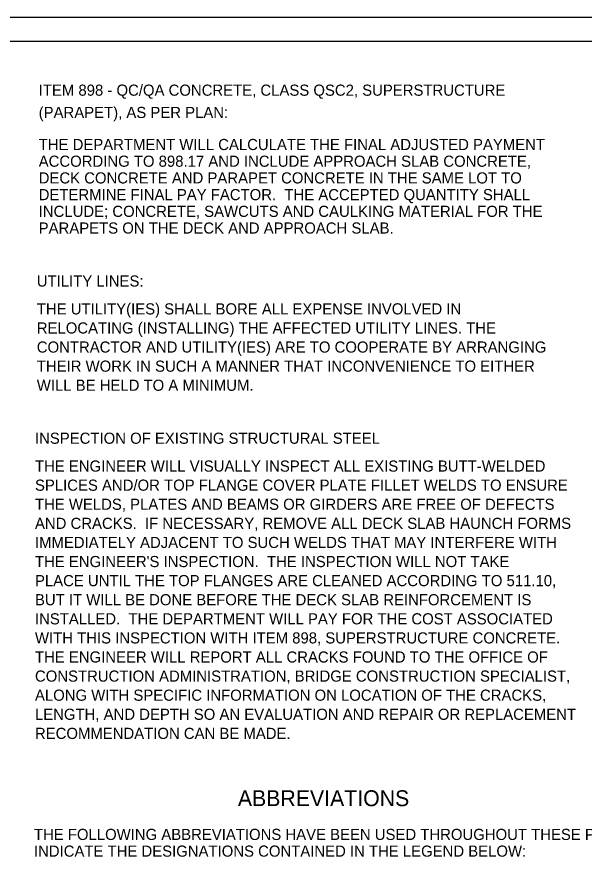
# Model space of a CAD drawing. Extents: x -70.8 to -34.9, y -11.1 to 10.9.
# Drawn here: x -46.33 to -39.19, y -0.16 to 10.66 of the extents above; entities that cross this region are included whole.
import ezdxf

# ---------------------------------------------------------------- set-up
doc = ezdxf.new("R2010")
doc.units = 0
for name, color, linetype in [('BR_P_Gen_Text', 7, 'Continuous'), ('SH_Border', 7, 'Continuous'), ('SH_Cut_Line', 7, 'Continuous'), ('SH_Data', 7, 'Continuous')]:
    doc.layers.add(name, color=color, linetype=linetype)

msp = doc.modelspace()

# ---------------------------------------------------------------- linework, layer by layer
at = {"layer": 'SH_Border'}
msp.add_lwpolyline([(-67.562, 10.356), (-36.062, 10.356), (-36.062, -10.644), (-67.562, -10.644)], close=True, dxfattribs=at)
at = {"layer": 'SH_Cut_Line'}
msp.add_lwpolyline([(-35.499, -10.994), (-69.499, -10.994), (-69.499, 10.656), (-35.499, 10.656)], close=True, dxfattribs=at)

# ---------------------------------------------------------------- texts
at = {"layer": 'BR_P_Gen_Text'}
for s, p in [('ITEM 898 - QC/QA CONCRETE, CLASS QSC2, SUPERSTRUCTURE', (-46.057, 9.669)), ('(PARAPET), AS PER PLAN:', (-46.057, 9.389)), ('THE DEPARTMENT WILL CALCULATE THE FINAL ADJUSTED PAYMENT ', (-46.057, 8.986)), ('ACCORDING TO 898.17 AND INCLUDE APPROACH SLAB CONCRETE, ', (-46.057, 8.776)), ('DECK CONCRETE AND PARAPET CONCRETE IN THE SAME LOT TO ', (-46.057, 8.566)), ('DETERMINE FINAL PAY FACTOR.  THE ACCEPTED QUANTITY SHALL ', (-46.057, 8.356)), ('INCLUDE; CONCRETE, SAWCUTS AND CAULKING MATERIAL FOR THE ', (-46.057, 8.146)), ('PARAPETS ON THE DECK AND APPROACH SLAB.', (-46.057, 7.936)), ('UTILITY LINES:', (-46.081, 7.27)), ('THE UTILITY(IES) SHALL BORE ALL EXPENSE INVOLVED IN ', (-46.081, 6.92)), ('RELOCATING (INSTALLING) THE AFFECTED UTILITY LINES. THE ', (-46.081, 6.68)), ('CONTRACTOR AND UTILITY(IES) ARE TO COOPERATE BY ARRANGING ', (-46.081, 6.44)), ('THEIR WORK IN SUCH A MANNER THAT INCONVENIENCE TO EITHER ', (-46.081, 6.2)), ('WILL BE HELD TO A MINIMUM.', (-46.081, 5.96)), ('INSPECTION OF EXISTING STRUCTURAL STEEL', (-46.104, 5.294)), ('THE ENGINEER WILL VISUALLY INSPECT ALL EXISTING BUTT-WELDED ', (-46.104, 4.944)), ('SPLICES AND/OR TOP FLANGE COVER PLATE FILLET WELDS TO ENSURE ', (-46.104, 4.704)), ('THE WELDS, PLATES AND BEAMS OR GIRDERS ARE FREE OF DEFECTS ', (-46.104, 4.464)), ('AND CRACKS.  IF NECESSARY, REMOVE ALL DECK SLAB HAUNCH FORMS ', (-46.104, 4.224)), ('IMMEDIATELY ADJACENT TO SUCH WELDS THAT MAY INTERFERE WITH ', (-46.104, 3.984)), ("THE ENGINEER'S INSPECTION.  THE INSPECTION WILL NOT TAKE ", (-46.104, 3.744)), ('PLACE UNTIL THE TOP FLANGES ARE CLEANED ACCORDING TO 511.10, ', (-46.104, 3.504)), ('BUT IT WILL BE DONE BEFORE THE DECK SLAB REINFORCEMENT IS ', (-46.104, 3.264)), ('INSTALLED.  THE DEPARTMENT WILL PAY FOR THE COST ASSOCIATED ', (-46.104, 3.024)), ('WITH THIS INSPECTION WITH ITEM 898, SUPERSTRUCTURE CONCRETE. ', (-46.104, 2.784)), ('THE ENGINEER WILL REPORT ALL CRACKS FOUND TO THE OFFICE OF ', (-46.104, 2.544)), ('CONSTRUCTION ADMINISTRATION, BRIDGE CONSTRUCTION SPECIALIST, ', (-46.104, 2.304)), ('ALONG WITH SPECIFIC INFORMATION ON LOCATION OF THE CRACKS, ', (-46.104, 2.064)), ('LENGTH, AND DEPTH SO AN EVALUATION AND REPAIR OR REPLACEMENT ', (-46.104, 1.824)), ('RECOMMENDATION CAN BE MADE.', (-46.104, 1.584))]:
    msp.add_text(s, height=0.14, dxfattribs=at).set_placement(p)
at = {"layer": 'SH_Data'}
for s, height, p in [('ABBREVIATIONS', 0.2, (-43.553, 0.739)), ('THE FOLLOWING ABBREVIATIONS HAVE BEEN USED THROUGHOUT THESE PLANS TO', 0.14, (-46.117, 0.314)), ('INDICATE THE DESIGNATIONS CONTAINED IN THE LEGEND BELOW:', 0.14, (-46.117, 0.104))]:
    msp.add_text(s, height=height, dxfattribs=at).set_placement(p)

doc.saveas('drawing.dxf')
